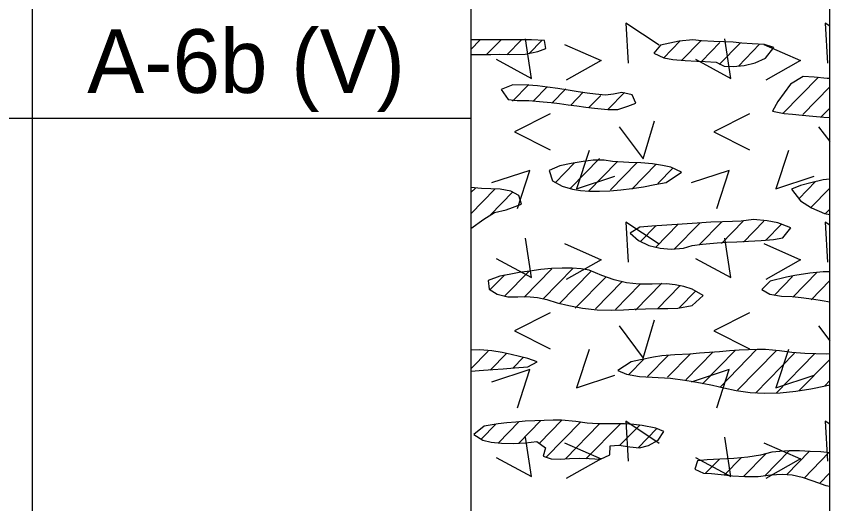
# Model space of a CAD drawing. Extents: x -0.01 to 0.83, y -0.63 to 1.27.
# Drawn here: x 0.7483 to 0.8333, y 0.45 to 0.501 of the extents above; entities that cross this region are included whole.
import ezdxf

# ---------------------------------------------------------------- set-up
doc = ezdxf.new("R2010")
doc.units = 0

msp = doc.modelspace()

# ---------------------------------------------------------------- linework, layer by layer
for points in [[(0, 0), (0.833332, 0), (0.833332, 1.274997), (0, 1.274997)], [(0, 0), (0.833332, 0), (0.833332, 1.274997), (0, 1.274997)], [(0, 0), (0.833332, 0), (0.833332, 1.274997), (0, 1.274997)], [(0, 0), (0.833332, 0), (0.833332, 1.274997), (0, 1.274997)], [(0, 0), (0.833332, 0), (0.833332, 1.274997), (0, 1.274997)], [(0.795832, 0.496961), (0.796757, 0.496951), (0.797925, 0.496971), (0.798816, 0.497009), (0.799915, 0.496966), (0.801515, 0.49701), (0.802823, 0.497267), (0.803666, 0.497587), (0.80354, 0.498425), (0.802165, 0.49851), (0.795832, 0.49851)], [(0.818216, 0.496316), (0.819444, 0.496258), (0.820325, 0.496217), (0.821453, 0.49615), (0.822286, 0.495736), (0.82324, 0.495691), (0.824378, 0.495797), (0.825554, 0.496085), (0.826624, 0.496589), (0.82749, 0.497686), (0.826513, 0.49799), (0.825239, 0.49809), (0.82413, 0.498154), (0.823236, 0.49826), (0.822257, 0.498279), (0.821211, 0.498303), (0.819948, 0.498395), (0.819024, 0.49851), (0.817611, 0.498371), (0.815663, 0.497927), (0.814958, 0.497089), (0.815983, 0.4966), (0.816947, 0.496425)], [(0.833053, 0.494462), (0.831709, 0.494574), (0.830539, 0.494675), (0.829246, 0.493855), (0.828567, 0.492942), (0.827924, 0.492054), (0.827345, 0.491028), (0.828579, 0.490802), (0.829451, 0.490702), (0.830451, 0.490605), (0.831549, 0.490509), (0.832716, 0.490413), (0.833332, 0.490361), (0.833332, 0.494453)], [(0.800664, 0.492159), (0.801881, 0.492153), (0.803392, 0.492024), (0.804229, 0.491928), (0.805103, 0.491818), (0.806004, 0.4917), (0.806919, 0.491579), (0.807838, 0.491461), (0.808747, 0.491351), (0.810142, 0.49121), (0.811186, 0.491221), (0.812223, 0.491566), (0.81308, 0.491851), (0.812673, 0.492753), (0.811597, 0.493001), (0.810749, 0.492802), (0.809892, 0.492719), (0.808847, 0.4928), (0.807995, 0.492911), (0.807033, 0.493056), (0.805997, 0.493219), (0.804922, 0.493386), (0.803843, 0.493543), (0.802797, 0.493675), (0.801817, 0.493768), (0.800202, 0.493776), (0.799007, 0.493303), (0.79974, 0.492261)], [(0.812326, 0.485654), (0.810635, 0.485773), (0.809773, 0.485907), (0.808601, 0.485913), (0.807553, 0.485769), (0.806321, 0.48557), (0.805133, 0.485327), (0.804031, 0.484806), (0.804359, 0.483746), (0.805363, 0.483178), (0.806466, 0.48288), (0.807303, 0.482729), (0.80824, 0.482653), (0.80926, 0.482644), (0.810349, 0.482695), (0.811489, 0.482798), (0.812666, 0.482945), (0.813863, 0.483128), (0.815063, 0.483341), (0.816252, 0.483575), (0.81783, 0.484656), (0.816735, 0.485155), (0.815852, 0.485358), (0.814797, 0.485515), (0.813609, 0.485618)], [(0.832654, 0.483842), (0.831362, 0.483532), (0.830275, 0.483258), (0.829339, 0.482864), (0.830265, 0.481664), (0.831418, 0.480901), (0.832792, 0.480322), (0.833332, 0.480223), (0.833332, 0.483932)], [(0.795832, 0.478745), (0.79719, 0.479736), (0.798312, 0.480437), (0.799509, 0.480708), (0.801112, 0.48131), (0.800861, 0.482194), (0.800021, 0.482669), (0.798893, 0.482864), (0.797908, 0.482893), (0.796943, 0.482951), (0.795832, 0.483033)], [(0.825375, 0.479688), (0.824078, 0.479539), (0.823187, 0.479481), (0.822142, 0.479457), (0.820907, 0.47942), (0.819474, 0.479328), (0.817918, 0.479208), (0.816318, 0.479088), (0.814751, 0.478995), (0.813476, 0.478895), (0.812472, 0.478255), (0.813366, 0.477494), (0.814436, 0.47699), (0.815612, 0.476702), (0.816749, 0.476596), (0.818067, 0.476709), (0.818959, 0.476984), (0.820031, 0.477128), (0.821573, 0.47725), (0.82253, 0.477308), (0.823615, 0.477367), (0.824832, 0.477428), (0.826183, 0.477494), (0.827451, 0.477602), (0.828416, 0.477778), (0.829268, 0.478833), (0.827909, 0.479349), (0.826788, 0.479549)], [(0.798854, 0.47378), (0.797634, 0.473319), (0.797728, 0.472423), (0.798587, 0.4719), (0.799696, 0.471603), (0.800742, 0.471613), (0.801652, 0.471627), (0.802809, 0.471544), (0.803766, 0.471336), (0.804856, 0.470987), (0.80606, 0.470691), (0.807509, 0.470416), (0.809046, 0.47023), (0.810517, 0.4702), (0.811769, 0.470257), (0.812889, 0.470298), (0.814075, 0.470333), (0.815527, 0.470374), (0.816416, 0.4704), (0.817445, 0.470431), (0.818967, 0.470705), (0.820111, 0.471741), (0.818963, 0.472409), (0.818099, 0.472677), (0.817169, 0.472873), (0.816265, 0.472978), (0.814793, 0.472919), (0.813435, 0.472922), (0.812104, 0.473072), (0.810802, 0.473375), (0.809527, 0.473835), (0.808198, 0.474385), (0.807356, 0.474545), (0.806403, 0.474619), (0.805364, 0.474619), (0.804267, 0.474559), (0.803138, 0.47445), (0.802006, 0.474306), (0.800896, 0.474137), (0.799837, 0.473958)], [(0.832629, 0.474226), (0.831261, 0.474088), (0.829688, 0.473823), (0.828826, 0.47365), (0.82712, 0.473239), (0.826226, 0.47237), (0.827084, 0.471878), (0.828308, 0.471692), (0.829408, 0.471626), (0.830335, 0.471538), (0.831655, 0.471355), (0.832526, 0.471212), (0.833332, 0.47107), (0.833332, 0.474219)], [(0.795832, 0.463823), (0.797147, 0.463933), (0.798141, 0.464006), (0.799224, 0.464083), (0.800394, 0.464168), (0.80179, 0.464291), (0.802748, 0.464805), (0.801793, 0.465147), (0.800911, 0.465361), (0.800027, 0.465581), (0.79909, 0.465788), (0.798029, 0.465953), (0.79677, 0.466049), (0.795832, 0.466028)], [(0.828162, 0.461575), (0.82978, 0.461744), (0.831374, 0.461996), (0.832902, 0.462308), (0.833332, 0.462412), (0.833332, 0.465653), (0.832951, 0.46562), (0.831885, 0.465642), (0.830714, 0.465694), (0.829383, 0.465797), (0.828069, 0.465966), (0.826619, 0.466085), (0.825765, 0.466087), (0.824843, 0.46606), (0.823868, 0.466009), (0.822856, 0.465941), (0.82182, 0.465862), (0.820774, 0.465777), (0.819735, 0.465695), (0.818715, 0.465619), (0.817148, 0.465524), (0.815785, 0.465432), (0.814914, 0.465298), (0.813574, 0.465024), (0.812595, 0.464811), (0.811206, 0.463893), (0.812105, 0.463531), (0.813452, 0.463285), (0.814789, 0.463194), (0.816678, 0.463092), (0.818181, 0.462891), (0.819046, 0.462745), (0.820004, 0.462566), (0.821067, 0.462352), (0.82225, 0.4621), (0.823565, 0.461809), (0.825013, 0.461583), (0.826559, 0.461513)], [(0.797084, 0.456594), (0.797938, 0.456415), (0.799042, 0.456303), (0.800285, 0.456269), (0.801555, 0.456324), (0.802742, 0.456478), (0.803614, 0.455817), (0.803377, 0.454919), (0.804221, 0.454649), (0.805167, 0.45463), (0.806129, 0.454686), (0.807202, 0.454717), (0.808182, 0.454686), (0.809387, 0.454613), (0.81037, 0.455078), (0.81038, 0.456025), (0.811296, 0.456088), (0.812442, 0.455901), (0.813463, 0.455795), (0.814379, 0.45605), (0.815394, 0.456593), (0.816006, 0.457505), (0.81517, 0.457878), (0.813738, 0.458154), (0.812849, 0.458247), (0.811872, 0.458305), (0.810001, 0.458307), (0.809104, 0.458326), (0.808002, 0.4584), (0.806784, 0.458557), (0.805305, 0.458687), (0.804427, 0.4587), (0.803488, 0.458684), (0.802511, 0.458643), (0.801521, 0.458582), (0.80054, 0.458503), (0.799593, 0.458412), (0.798702, 0.458313), (0.797221, 0.45809), (0.796138, 0.457212)], [(0.832407, 0.455374), (0.831293, 0.455439), (0.830172, 0.455476), (0.829096, 0.455478), (0.828115, 0.455439), (0.827281, 0.455351), (0.826083, 0.455051), (0.824762, 0.454825), (0.823296, 0.454688), (0.821831, 0.454606), (0.820509, 0.454547), (0.819505, 0.454448), (0.819224, 0.453584), (0.820125, 0.453165), (0.820967, 0.453114), (0.821997, 0.453014), (0.823181, 0.452884), (0.824476, 0.452796), (0.825838, 0.452821), (0.82719, 0.452985), (0.828356, 0.453051), (0.829402, 0.452971), (0.830435, 0.452738), (0.831559, 0.452347), (0.832909, 0.451857), (0.833332, 0.451781), (0.833332, 0.455299)]]:
    msp.add_lwpolyline(points, close=True)
for points in [[(0.749999, 1.220831), (0.749999, -0.621832)], [(0.749999, 1.220831), (0.749999, -0.621832)], [(0.795832, 1.220831), (0.795832, -0.621832)], [(0.833332, -0.621832), (0.833332, 1.138431)], [(0.815512, 0.497942), (0.812012, 0.500255), (0.812262, 0.496067)], [(0.833332, 0.499933), (0.832845, 0.500255), (0.833095, 0.496067)], [(0.795832, 0.49748), (0.796808, 0.49848)], [(0.798985, 0.498498), (0.797473, 0.49695)], [(0.798466, 0.49646), (0.802154, 0.49446), (0.801529, 0.498585)], [(0.801161, 0.498516), (0.799593, 0.496909)], [(0.803281, 0.498476), (0.801883, 0.497043)], [(0.817701, 0.498374), (0.815961, 0.496591)], [(0.819878, 0.498392), (0.817852, 0.496315)], [(0.8193, 0.49646), (0.822987, 0.49446), (0.822362, 0.498585)], [(0.821854, 0.498204), (0.819972, 0.496275)], [(0.824002, 0.498192), (0.821778, 0.495913)], [(0.805617, 0.498005), (0.809456, 0.496322), (0.805806, 0.49426)], [(0.826007, 0.498034), (0.823783, 0.495755)], [(0.82645, 0.498005), (0.83029, 0.496322), (0.826639, 0.49426)], [(0.832167, 0.494588), (0.828441, 0.490771)], [(0.801877, 0.493815), (0.800195, 0.492092)], [(0.803798, 0.493571), (0.80237, 0.492108)], [(0.805745, 0.493353), (0.804291, 0.491863)], [(0.80758, 0.49302), (0.806268, 0.491675)], [(0.833332, 0.493569), (0.830521, 0.49069)], [(0.809414, 0.492687), (0.808159, 0.491401)], [(0.811876, 0.492997), (0.810165, 0.491244)], [(0.833332, 0.491356), (0.832451, 0.490454)], [(0.804125, 0.490747), (0.800375, 0.488872), (0.804125, 0.486997)], [(0.824958, 0.490747), (0.821208, 0.488872), (0.824958, 0.486997)], [(0.724999, 0.490291), (0.749999, 0.490291)], [(0.749999, 0.490291), (0.795832, 0.490291)], [(0.811342, 0.489406), (0.813842, 0.486031), (0.815029, 0.490031)], [(0.832175, 0.489406), (0.833332, 0.487845)], [(0.808181, 0.486916), (0.806868, 0.482916), (0.810868, 0.484228)], [(0.829014, 0.486916), (0.827702, 0.482916), (0.831702, 0.484228)], [(0.804649, 0.483537), (0.806674, 0.485612)], [(0.806256, 0.482971), (0.809278, 0.486068)], [(0.80809, 0.482637), (0.811113, 0.485735)], [(0.810409, 0.482801), (0.813175, 0.485636)], [(0.812643, 0.482878), (0.815181, 0.485478)], [(0.800689, 0.480835), (0.802002, 0.484835), (0.798002, 0.483523)], [(0.815361, 0.48345), (0.816987, 0.485115)], [(0.821523, 0.480835), (0.822835, 0.484835), (0.818835, 0.483523)], [(0.796303, 0.482991), (0.795832, 0.482508)], [(0.798338, 0.482863), (0.795832, 0.480295)], [(0.830098, 0.481875), (0.831838, 0.483658)], [(0.831305, 0.480901), (0.833332, 0.482977)], [(0.797862, 0.480163), (0.800229, 0.482589)], [(0.832854, 0.480274), (0.833332, 0.480763)], [(0.815512, 0.477109), (0.812012, 0.479422), (0.812262, 0.475234)], [(0.819696, 0.477035), (0.822034, 0.479432)], [(0.822015, 0.477198), (0.824297, 0.479537)], [(0.824306, 0.477333), (0.826445, 0.479525)], [(0.833332, 0.4791), (0.832845, 0.479422), (0.833095, 0.475234)], [(0.815192, 0.479059), (0.813538, 0.477363)], [(0.815145, 0.476797), (0.817482, 0.479192)], [(0.817092, 0.47658), (0.819744, 0.479297)], [(0.826625, 0.477497), (0.828336, 0.47925)], [(0.798466, 0.475627), (0.802154, 0.473627), (0.801529, 0.477752)], [(0.8193, 0.475627), (0.822987, 0.473627), (0.822362, 0.477752)], [(0.805617, 0.477172), (0.809456, 0.475488), (0.805806, 0.473427)], [(0.82645, 0.477172), (0.83029, 0.475488), (0.826639, 0.473427)], [(0.799328, 0.471654), (0.801951, 0.474342)], [(0.801419, 0.471583), (0.804299, 0.474535)], [(0.806532, 0.474611), (0.803395, 0.471396)], [(0.799375, 0.473915), (0.797863, 0.472366)], [(0.805059, 0.470887), (0.808397, 0.474308)], [(0.809973, 0.47371), (0.806747, 0.470404)], [(0.827512, 0.471762), (0.82945, 0.473748)], [(0.832025, 0.474175), (0.829489, 0.471575)], [(0.811636, 0.473202), (0.808841, 0.470338)], [(0.813527, 0.472927), (0.810936, 0.470273)], [(0.813032, 0.470206), (0.815789, 0.473032)], [(0.815342, 0.470361), (0.817681, 0.472757)], [(0.831379, 0.4713), (0.833332, 0.4733)], [(0.817605, 0.470466), (0.819344, 0.472249)], [(0.833327, 0.471084), (0.833332, 0.471088)], [(0.804125, 0.469914), (0.800375, 0.468039), (0.804125, 0.466164)], [(0.824958, 0.469914), (0.821208, 0.468039), (0.824958, 0.466164)], [(0.811342, 0.468573), (0.813842, 0.465198), (0.815029, 0.469198)], [(0.832175, 0.468573), (0.833332, 0.467011)], [(0.797655, 0.465936), (0.795832, 0.464067)], [(0.808181, 0.466082), (0.806868, 0.462082), (0.810868, 0.463395)], [(0.818285, 0.462915), (0.821137, 0.465837)], [(0.820035, 0.462495), (0.823455, 0.466)], [(0.825691, 0.466078), (0.82184, 0.462132)], [(0.827752, 0.465977), (0.823702, 0.461828)], [(0.829014, 0.466082), (0.827702, 0.462082), (0.831702, 0.463395)], [(0.799604, 0.46572), (0.797864, 0.463938)], [(0.801295, 0.465241), (0.800268, 0.464189)], [(0.813923, 0.465084), (0.812354, 0.463476)], [(0.814303, 0.46326), (0.816499, 0.46551)], [(0.816395, 0.463191), (0.818789, 0.465645)], [(0.829644, 0.465703), (0.825565, 0.461525)], [(0.831735, 0.465633), (0.827743, 0.461543)], [(0.833332, 0.465056), (0.830118, 0.461764)], [(0.800689, 0.460002), (0.802002, 0.464002), (0.798002, 0.462689)], [(0.821523, 0.460002), (0.822835, 0.464002), (0.818835, 0.462689)], [(0.832808, 0.462307), (0.833332, 0.462843)], [(0.798444, 0.458276), (0.796912, 0.456706)], [(0.79871, 0.456336), (0.800849, 0.458528)], [(0.800827, 0.456293), (0.803111, 0.458633)], [(0.805344, 0.458708), (0.802987, 0.456292)], [(0.80367, 0.454781), (0.807321, 0.458521)], [(0.805714, 0.454662), (0.809241, 0.458276)], [(0.811418, 0.458293), (0.807854, 0.454641)], [(0.811407, 0.45607), (0.81348, 0.458194)], [(0.815512, 0.456276), (0.812012, 0.458588), (0.812262, 0.454401)], [(0.833332, 0.458267), (0.832845, 0.458588), (0.833095, 0.454401)], [(0.815282, 0.457828), (0.813313, 0.45581)], [(0.798466, 0.454793), (0.802154, 0.452793), (0.801529, 0.456918)], [(0.8193, 0.454793), (0.822987, 0.452793), (0.822362, 0.456918)], [(0.805617, 0.456339), (0.809456, 0.454655), (0.805806, 0.452593)], [(0.82645, 0.456339), (0.83029, 0.454655), (0.826639, 0.452593)], [(0.824327, 0.452806), (0.82666, 0.455196)], [(0.829094, 0.455478), (0.826565, 0.452886)], [(0.828848, 0.453013), (0.831218, 0.455441)], [(0.833245, 0.455306), (0.830651, 0.452647)], [(0.820346, 0.453152), (0.821763, 0.454603)], [(0.822335, 0.452977), (0.824076, 0.454761)], [(0.833332, 0.453181), (0.832267, 0.45209)]]:
    msp.add_lwpolyline(points)

# ---------------------------------------------------------------- texts
msp.add_text('A-6b (V)', height=0.0066667).set_placement((0.755748, 0.492937))

doc.saveas('drawing.dxf')
